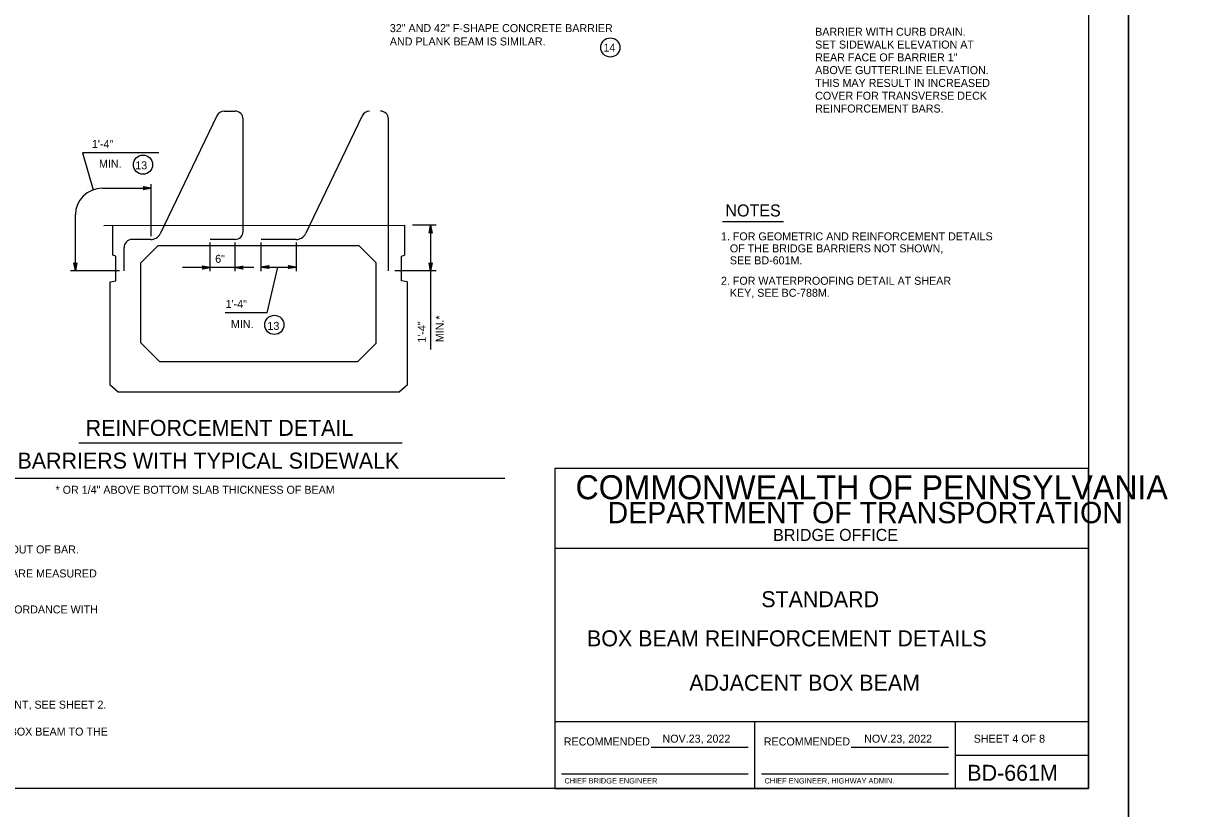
# Model space of a CAD drawing. Extents: x 639331 to 643089, y 299088 to 300975.
# Drawn here: x 641819.9 to 642261.4, y 300283.2 to 300577.6 of the extents above; entities that cross this region are included whole.
import ezdxf

# ---------------------------------------------------------------- set-up
doc = ezdxf.new("R2010")
doc.units = 0
for name, color, linetype in [('1', 7, 'Continuous'), ('DATES', 7, 'Continuous'), ('PLT-BNDY', 7, 'Continuous'), ('SIGNATORY TITLES', 7, 'Continuous')]:
    doc.layers.add(name, color=color, linetype=linetype)

msp = doc.modelspace()

# ---------------------------------------------------------------- linework, layer by layer
at = {"layer": '1'}
for p, q in [((642219.06, 300854.66), (642219.06, 300290.66)), ((641895.08, 300544.78), (641899.17, 300544.78)), ((641892.35, 300543.02), (641871.15, 300498.66)), ((641902.17, 300499.6), (641902.17, 300541.78)), ((641946.83, 300543.02), (641925.63, 300498.66)), ((641956.65, 300484.82), (641956.65, 300541.78)), ((641870.65, 300529.13), (641841.95, 300529.13)), ((641841.95, 300529.13), (641845.99, 300515.23)), ((641849.32, 300515.8), (641867.74, 300515.82)), ((641867.74, 300497.81), (641867.74, 300517.37)), ((641839.33, 300484.82), (641839.33, 300505.8)), ((641849.99, 300501.8), (641962.7, 300501.92)), ((641853.33, 300490.68), (641853.33, 300501.81)), ((641962.7, 300501.92), (641962.7, 300490.68)), ((641974.6, 300501.92), (641965.65, 300501.92)), ((641972.47, 300501.92), (641972.47, 300484.82)), ((642081.88, 300503.38), (642104.82, 300503.38)), ((641867.57, 300496.6), (641860.55, 300496.6)), ((641899.17, 300496.6), (641889.79, 300496.6)), ((641889.79, 300484.74), (641889.79, 300495.53)), ((641899.17, 300484.77), (641899.17, 300495.53)), ((641922.05, 300496.6), (641908.92, 300496.6)), ((641908.92, 300484.77), (641908.92, 300495.5)), ((641922.05, 300495.5), (641922.05, 300484.77)), ((641857.55, 300484.82), (641857.55, 300493.6)), ((641870.21, 300494.18), (641863.83, 300487.81)), ((641945.7, 300494.18), (641870.21, 300494.18)), ((641952.08, 300487.81), (641945.7, 300494.18)), ((641854.45, 300490.31), (641853.33, 300490.68)), ((641854.45, 300481.06), (641854.45, 300490.31)), ((641863.83, 300457.81), (641863.83, 300487.81)), ((641952.08, 300457.68), (641952.08, 300487.81)), ((641961.58, 300490.31), (641962.7, 300490.68)), ((641961.58, 300481.06), (641961.58, 300490.31)), ((641855.8, 300484.82), (641837.47, 300484.82)), ((641906.2, 300486.05), (641879.43, 300486.05)), ((641908.92, 300486.26), (641922.05, 300486.26)), ((641911.24, 300469.1), (641915.18, 300486.26)), ((641974.6, 300484.82), (641959.09, 300484.82)), ((641972.47, 300484.82), (641972.47, 300455.34)), ((641852.33, 300480.68), (641854.45, 300481.06)), ((641852.33, 300441.93), (641852.33, 300480.68)), ((641963.7, 300480.68), (641961.58, 300481.06)), ((641963.7, 300480.68), (641963.7, 300441.93)), ((641911.24, 300469.1), (641895.52, 300469.1)), ((641870.95, 300450.68), (641863.83, 300457.81)), ((641952.08, 300457.68), (641945.08, 300450.68)), ((641945.08, 300450.68), (641870.95, 300450.68)), ((641855.33, 300439.31), (641852.33, 300441.93)), ((641960.7, 300439.31), (641855.33, 300439.31)), ((641963.7, 300441.93), (641960.7, 300439.31)), ((641840.67, 300420.31), (641961.82, 300420.31)), ((642219.06, 300410.66), (642019.06, 300410.66)), ((642019.06, 300410.66), (642019.06, 300290.66)), ((642219.06, 300290.66), (642219.06, 300410.66)), ((641797.28, 300407.06), (642000.3, 300407.06)), ((642219.06, 300380.66), (642019.06, 300380.66)), ((642219.06, 300315.66), (642019.06, 300315.66)), ((642094.06, 300290.66), (642094.06, 300315.66)), ((642169.06, 300315.66), (642169.06, 300290.66)), ((642055.15, 300306.16), (642091.56, 300306.16)), ((642130.15, 300306.16), (642166.56, 300306.16)), ((642169.06, 300303.16), (642219.06, 300303.16)), ((642021.56, 300296.16), (642091.56, 300296.16)), ((642096.56, 300296.16), (642166.56, 300296.16)), ((642219.06, 300290.66), (641433.06, 300290.66)), ((642019.06, 300290.66), (642219.06, 300290.66))]:
    msp.add_line(p, q, dxfattribs=at)
for points in [[(641867.74, 300515.82), (641864.76, 300515.26), (641864.88, 300515.34), (641864.99, 300515.42), (641865.05, 300515.52), (641865.11, 300515.62), (641865.13, 300515.72), (641865.14, 300515.82), (641865.13, 300515.92), (641865.11, 300516.02), (641865.05, 300516.12), (641864.99, 300516.22), (641864.87, 300516.3), (641864.76, 300516.38), (641867.74, 300515.82), (641864.87, 300516.3), (641864.99, 300516.22), (641867.74, 300515.82), (641865.05, 300516.12), (641865.11, 300516.02), (641867.74, 300515.82), (641865.13, 300515.92), (641865.14, 300515.82), (641867.74, 300515.82), (641865.13, 300515.72), (641865.11, 300515.62), (641867.74, 300515.82), (641865.05, 300515.52), (641864.99, 300515.42), (641867.74, 300515.82), (641864.88, 300515.34)], [(641972.47, 300501.92), (641973.03, 300498.94), (641972.95, 300499.05), (641972.87, 300499.17), (641972.77, 300499.23), (641972.67, 300499.29), (641972.57, 300499.3), (641972.47, 300499.32), (641972.37, 300499.3), (641972.27, 300499.29), (641972.17, 300499.23), (641972.07, 300499.17), (641971.99, 300499.05), (641971.91, 300498.94), (641972.47, 300501.92), (641971.99, 300499.05), (641972.07, 300499.17), (641972.47, 300501.92), (641972.17, 300499.23), (641972.27, 300499.29), (641972.47, 300501.92), (641972.37, 300499.3), (641972.47, 300499.32), (641972.47, 300501.92), (641972.57, 300499.3), (641972.67, 300499.29), (641972.47, 300501.92), (641972.77, 300499.23), (641972.87, 300499.17), (641972.47, 300501.92), (641972.95, 300499.05)], [(641839.33, 300484.82), (641838.77, 300487.8), (641838.85, 300487.69), (641838.93, 300487.57), (641839.03, 300487.51), (641839.13, 300487.45), (641839.23, 300487.44), (641839.33, 300487.42), (641839.43, 300487.44), (641839.53, 300487.45), (641839.63, 300487.51), (641839.73, 300487.57), (641839.81, 300487.69), (641839.89, 300487.8), (641839.33, 300484.82), (641839.81, 300487.69), (641839.73, 300487.57), (641839.33, 300484.82), (641839.63, 300487.51), (641839.53, 300487.45), (641839.33, 300484.82), (641839.43, 300487.44), (641839.33, 300487.42), (641839.33, 300484.82), (641839.23, 300487.44), (641839.13, 300487.45), (641839.33, 300484.82), (641839.03, 300487.51), (641838.93, 300487.57), (641839.33, 300484.82), (641838.85, 300487.69)], [(641889.79, 300486.05), (641886.81, 300485.49), (641886.92, 300485.57), (641887.04, 300485.65), (641887.1, 300485.75), (641887.16, 300485.85), (641887.17, 300485.95), (641887.19, 300486.05), (641887.17, 300486.15), (641887.16, 300486.25), (641887.1, 300486.35), (641887.04, 300486.45), (641886.92, 300486.53), (641886.81, 300486.61), (641889.79, 300486.05), (641886.92, 300486.53), (641887.04, 300486.45), (641889.79, 300486.05), (641887.1, 300486.35), (641887.16, 300486.25), (641889.79, 300486.05), (641887.17, 300486.15), (641887.19, 300486.05), (641889.79, 300486.05), (641887.17, 300485.95), (641887.16, 300485.85), (641889.79, 300486.05), (641887.1, 300485.75), (641887.04, 300485.65), (641889.79, 300486.05), (641886.92, 300485.57)], [(641899.17, 300486.05), (641902.15, 300486.61), (641902.03, 300486.53), (641901.92, 300486.45), (641901.86, 300486.35), (641901.8, 300486.25), (641901.78, 300486.15), (641901.77, 300486.05), (641901.78, 300485.95), (641901.8, 300485.85), (641901.86, 300485.75), (641901.92, 300485.65), (641902.03, 300485.57), (641902.15, 300485.49), (641899.17, 300486.05), (641902.03, 300485.57), (641901.92, 300485.65), (641899.17, 300486.05), (641901.86, 300485.75), (641901.8, 300485.85), (641899.17, 300486.05), (641901.78, 300485.95), (641901.77, 300486.05), (641899.17, 300486.05), (641901.78, 300486.15), (641901.8, 300486.25), (641899.17, 300486.05), (641901.86, 300486.35), (641901.92, 300486.45), (641899.17, 300486.05), (641902.03, 300486.53)], [(641908.92, 300486.26), (641911.9, 300486.82), (641911.79, 300486.74), (641911.67, 300486.66), (641911.61, 300486.56), (641911.55, 300486.46), (641911.54, 300486.36), (641911.52, 300486.26), (641911.54, 300486.16), (641911.55, 300486.06), (641911.61, 300485.96), (641911.67, 300485.86), (641911.79, 300485.78), (641911.9, 300485.7), (641908.92, 300486.26), (641911.79, 300485.78), (641911.67, 300485.86), (641908.92, 300486.26), (641911.61, 300485.96), (641911.55, 300486.06), (641908.92, 300486.26), (641911.54, 300486.16), (641911.52, 300486.26), (641908.92, 300486.26), (641911.54, 300486.36), (641911.55, 300486.46), (641908.92, 300486.26), (641911.61, 300486.56), (641911.67, 300486.66), (641908.92, 300486.26), (641911.79, 300486.74)], [(641922.05, 300486.26), (641919.07, 300485.7), (641919.19, 300485.78), (641919.3, 300485.86), (641919.36, 300485.96), (641919.42, 300486.06), (641919.44, 300486.16), (641919.45, 300486.26), (641919.44, 300486.36), (641919.42, 300486.46), (641919.36, 300486.56), (641919.3, 300486.66), (641919.19, 300486.74), (641919.07, 300486.82), (641922.05, 300486.26), (641919.19, 300486.74), (641919.3, 300486.66), (641922.05, 300486.26), (641919.36, 300486.56), (641919.42, 300486.46), (641922.05, 300486.26), (641919.44, 300486.36), (641919.45, 300486.26), (641922.05, 300486.26), (641919.44, 300486.16), (641919.42, 300486.06), (641922.05, 300486.26), (641919.36, 300485.96), (641919.3, 300485.86), (641922.05, 300486.26), (641919.19, 300485.78)], [(641972.47, 300484.82), (641971.91, 300487.8), (641971.99, 300487.69), (641972.07, 300487.57), (641972.17, 300487.51), (641972.27, 300487.45), (641972.37, 300487.44), (641972.47, 300487.42), (641972.57, 300487.44), (641972.67, 300487.45), (641972.77, 300487.51), (641972.87, 300487.57), (641972.95, 300487.69), (641973.03, 300487.8), (641972.47, 300484.82), (641972.95, 300487.69), (641972.87, 300487.57), (641972.47, 300484.82), (641972.77, 300487.51), (641972.67, 300487.45), (641972.47, 300484.82), (641972.57, 300487.44), (641972.47, 300487.42), (641972.47, 300484.82), (641972.37, 300487.44), (641972.27, 300487.45), (641972.47, 300484.82), (641972.17, 300487.51), (641972.07, 300487.57), (641972.47, 300484.82), (641971.99, 300487.69)]]:
    msp.add_lwpolyline(points, dxfattribs=at)
for centre in [(642039.85, 300568.64), (641864.65, 300524.68), (641913.89, 300464.55)]:
    msp.add_circle(centre, 3.6, dxfattribs=at)
for centre, radius, start, end in [((641895.08, 300541.78), 3, 90, 155.6561), ((641899.17, 300541.78), 3, 0, 90), ((641949.56, 300541.78), 3, 90, 155.6561), ((641953.65, 300541.78), 3, 0, 90), ((641849.33, 300505.8), 10, 90.0597, 180), ((641860.55, 300493.6), 3, 90, 180), ((641867.57, 300500.72), 4.12, 270, 330.0819), ((641899.17, 300499.6), 3, 270, 360), ((641922.05, 300500.72), 4.12, 270, 330.0819)]:
    msp.add_arc(centre, radius, start, end, dxfattribs=at)
at = {"layer": 'PLT-BNDY'}
for points in [[(641393.06, 300869.66), (642234.06, 300869.66), (642234.06, 300275.66), (641393.06, 300275.66)], [(642234.06, 300869.66), (643075.06, 300869.66), (643075.06, 300275.66), (642234.06, 300275.66)]]:
    msp.add_lwpolyline(points, close=True, dxfattribs=at)

# ---------------------------------------------------------------- texts
at = {"layer": '1'}
for s, height, p in [('32" AND 42" F-SHAPE CONCRETE BARRIER ', 3, (641957.19, 300574.39)), ('   BARRIER WITH CURB DRAIN.', 3, (642113.28, 300573.03)), ('AND PLANK BEAM IS SIMILAR.', 3, (641957.19, 300569.39)), ('   SET SIDEWALK ELEVATION AT', 3, (642113.28, 300568.23)), ('14', 3, (642037.29, 300567.11)), ('   REAR FACE OF BARRIER 1"', 3, (642113.28, 300563.43)), ('   ABOVE GUTTERLINE ELEVATION.', 3, (642113.28, 300558.63)), ('   THIS MAY RESULT IN INCREASED', 3, (642113.28, 300553.83)), ('   COVER FOR TRANSVERSE DECK', 3, (642113.28, 300549.03)), ('   REINFORCEMENT BARS.', 3, (642113.28, 300544.23)), ('1\'-4"', 3, (641845.51, 300530.92)), ('13', 3, (641861.77, 300522.91)), ('NOTES', 4.5, (642082.98, 300505.23)), ('1. FOR GEOMETRIC AND REINFORCEMENT DETAILS', 3, (642081.31, 300496.27)), ('   OF THE BRIDGE BARRIERS NOT SHOWN,', 3, (642081.31, 300491.77)), ('6"', 3, (641891.73, 300487.84)), ('   SEE BD-601M.', 3, (642081.31, 300487.27)), ('2. FOR WATERPROOFING DETAIL AT SHEAR', 3, (642081.31, 300479.61)), ('   KEY, SEE BC-788M.', 3, (642081.31, 300475.11)), ('1\'-4"', 3, (641895.64, 300470.89)), ('13', 3, (641911.32, 300462.69)), ('REINFORCEMENT DETAIL', 6, (641843.17, 300422.94)), ('FOR BARRIERS WITH TYPICAL SIDEWALK', 6, (641798.46, 300410.64)), ('COMMONWEALTH OF PENNSYLVANIA', 9, (642026.81, 300399.16)), ('* OR 1/4" ABOVE BOTTOM SLAB THICKNESS OF BEAM', 3, (641831.88, 300401.21)), ('DEPARTMENT OF TRANSPORTATION', 8.0002, (642038.81, 300390.16)), ('BRIDGE OFFICE', 4.5, (642100.86, 300383.53)), ('1. REINFORCEMENT BAR DIMENSIONS ARE OUT TO OUT OF BAR.', 3, (641712.92, 300378.82)), ('2. DIMENSIONS ALONG CURVED PORTIONS OF BAR ARE MEASURED ', 3, (641712.92, 300369.82)), ('STANDARD', 6, (642096.43, 300358.66)), ('3. EPOXY COAT ALL REINFORCEMENT STEEL IN ACCORDANCE WITH', 3, (641712.92, 300356.32)), ('BOX BEAM REINFORCEMENT DETAILS', 6, (642031.11, 300343.98)), ('ADJACENT BOX BEAM', 6, (642069.43, 300327.33)), ('1. FOR BEAM DIMENSIONS AND BEAM REINFORCEMENT, SEE SHEET 2.', 3, (641711.64, 300320.6)), ('2. REINFORCEMENT BARS PROTRUDING FROM THE BOX BEAM TO THE', 3, (641711.95, 300310.49)), ('SHEET 4 OF 8', 3, (642176.05, 300307.84)), ('RECOMMENDED', 3, (642022.39, 300306.78)), ('RECOMMENDED', 3, (642097.39, 300306.78)), ('BD-661M', 6, (642173.68, 300293.53))]:
    msp.add_text(s, height=height, dxfattribs=at).set_placement(p)
for s, rotation, p in [('MIN.', 360, (641848.16, 300523.51)), ('MIN.', 360, (641897.63, 300463.35)), ('1\'-4"', 90, (641970.68, 300457.9)), ('MIN.*', 90, (641977.32, 300458.06))]:
    msp.add_text(s, height=3, rotation=rotation, dxfattribs=at).set_placement(p)
at = {"layer": 'DATES'}
for p in [(642059.4, 300307.84), (642135.01, 300307.84)]:
    msp.add_text('NOV.23, 2022', height=3, dxfattribs=at).set_placement(p)
at = {"layer": 'SIGNATORY TITLES'}
for s, p in [('CHIEF BRIDGE ENGINEER', (642022.65, 300292.53)), ('CHIEF ENGINEER, HIGHWAY ADMIN.', (642097.65, 300292.53))]:
    msp.add_text(s, height=2, dxfattribs=at).set_placement(p)

doc.saveas('drawing.dxf')
